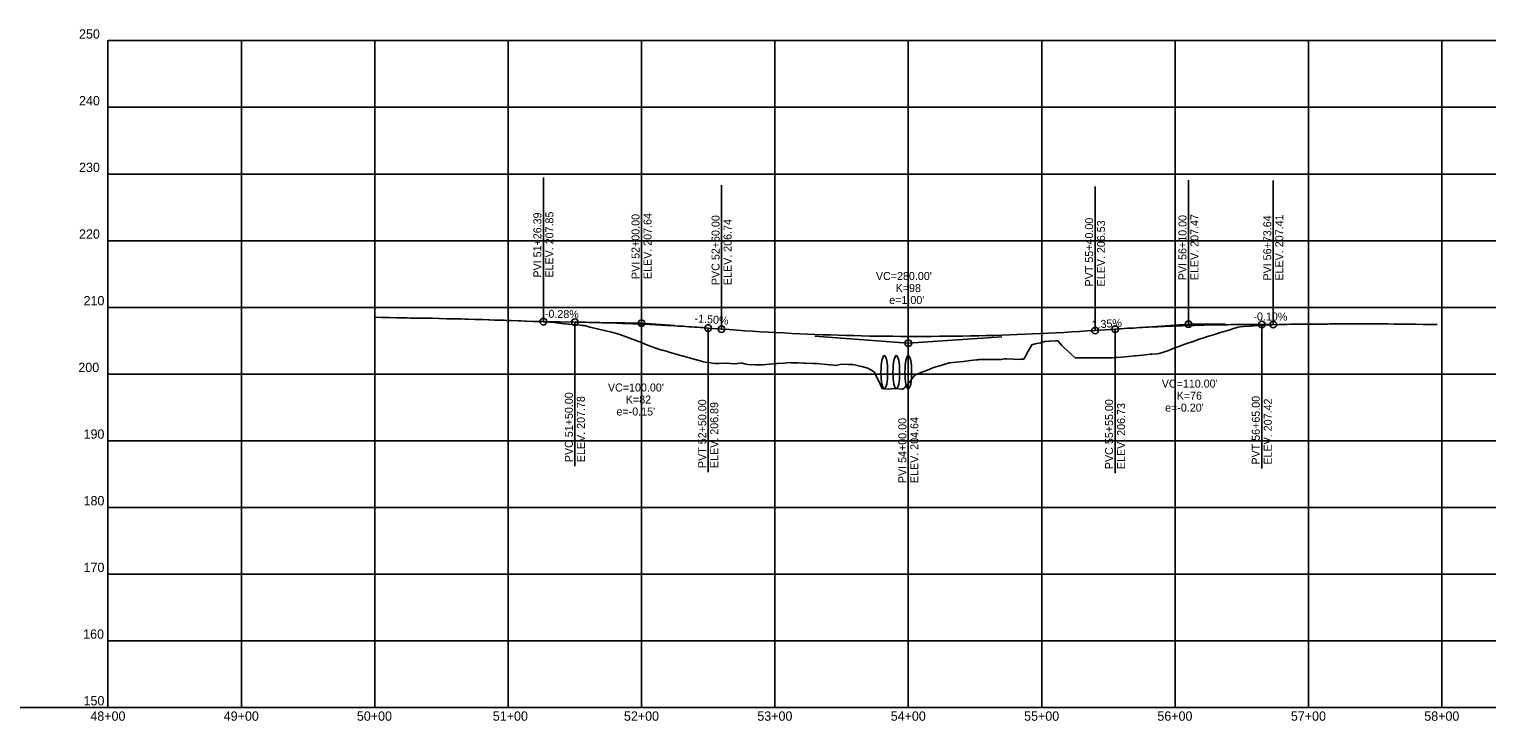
# Model space of a CAD drawing. Extents: x 1138442 to 1165793, y 1654070 to 1657687.
# Drawn here: x 1148047 to 1149139, y 1655043 to 1655562 of the extents above; entities that cross this region are included whole.
import ezdxf

# ---------------------------------------------------------------- set-up
doc = ezdxf.new("R2010")
doc.units = 0
for name, color, linetype in [('B_Dimensions', 7, 'Continuous'), ('R_Axis', 7, 'Continuous'), ('R_Axis Annot', 7, 'Continuous'), ('R_Concrete', 7, 'Continuous'), ('R_Grid', 7, 'Continuous'), ('R_No Plot', 7, 'Continuous'), ('R_Proposed Const Limits_Hand', 7, 'Continuous'), ('R_Vert Alg Annot', 7, 'Continuous')]:
    doc.layers.add(name, color=color, linetype=linetype)

msp = doc.modelspace()

# ---------------------------------------------------------------- linework, layer by layer
at = {"layer": 'B_Dimensions'}
for p, q in [((1148432.1, 1655342.7), (1148455.7, 1655342.3)), ((1148480.7, 1655342), (1148505.7, 1655341.6)), ((1148505.7, 1655341.6), (1148530.7, 1655339.7)), ((1148888.2, 1655338.9), (1148915.7, 1655340.8)), ((1148915.7, 1655340.8), (1148943.2, 1655340.7)), ((1148555.7, 1655337.9), (1148565.7, 1655337.1)), ((1148635.7, 1655331.9), (1148705.7, 1655326.6)), ((1148705.7, 1655326.6), (1148775.7, 1655331.3)), ((1148845.7, 1655336.1), (1148860.7, 1655337.1)), ((1148970.7, 1655340.5), (1148979.3, 1655340.5))]:
    msp.add_line(p, q, dxfattribs=at)
for points in [[(1148455.7, 1655342.3), (1148457.8, 1655342.3), (1148459.9, 1655342.3), (1148462, 1655342.2), (1148464, 1655342.2), (1148466.1, 1655342.1), (1148468.2, 1655342.1), (1148470.3, 1655342.1), (1148472.4, 1655342), (1148474.5, 1655342), (1148476.5, 1655341.9), (1148478.6, 1655341.8), (1148480.7, 1655341.8), (1148482.8, 1655341.7), (1148484.9, 1655341.7), (1148487, 1655341.6), (1148489, 1655341.5), (1148491.1, 1655341.4), (1148493.2, 1655341.4), (1148495.3, 1655341.3), (1148497.4, 1655341.2), (1148499.5, 1655341.1), (1148501.5, 1655341), (1148503.6, 1655340.9), (1148507.8, 1655340.8), (1148509.9, 1655340.7), (1148512, 1655340.6), (1148514, 1655340.5), (1148516.1, 1655340.4), (1148518.2, 1655340.3), (1148520.3, 1655340.1), (1148522.4, 1655340), (1148524.5, 1655339.9), (1148526.5, 1655339.8), (1148528.6, 1655339.7), (1148530.7, 1655339.6), (1148532.8, 1655339.4), (1148534.9, 1655339.3), (1148537, 1655339.2), (1148539, 1655339), (1148541.1, 1655338.9), (1148543.2, 1655338.8), (1148545.3, 1655338.6), (1148547.4, 1655338.5), (1148549.5, 1655338.3), (1148551.5, 1655338.2), (1148553.6, 1655338), (1148555.7, 1655337.9)], [(1148565.7, 1655337.1), (1148571.5, 1655336.7), (1148577.4, 1655336.3), (1148583.2, 1655335.9), (1148589, 1655335.5), (1148594.9, 1655335.1), (1148600.7, 1655334.8), (1148606.5, 1655334.5), (1148612.4, 1655334.2), (1148618.2, 1655333.9), (1148624, 1655333.6), (1148629.9, 1655333.4), (1148635.7, 1655333.1), (1148641.5, 1655332.9), (1148647.4, 1655332.7), (1148653.2, 1655332.5), (1148659, 1655332.3), (1148664.9, 1655332.2), (1148670.7, 1655332.1), (1148676.5, 1655331.9), (1148682.4, 1655331.8), (1148688.2, 1655331.8), (1148694, 1655331.7), (1148699.9, 1655331.6), (1148711.5, 1655331.6), (1148717.4, 1655331.6), (1148723.2, 1655331.6), (1148729, 1655331.7), (1148734.9, 1655331.7), (1148740.7, 1655331.8), (1148746.5, 1655331.9), (1148752.4, 1655332), (1148758.2, 1655332.1), (1148764, 1655332.3), (1148769.9, 1655332.4), (1148775.7, 1655332.6), (1148781.5, 1655332.8), (1148787.4, 1655333), (1148793.2, 1655333.2), (1148799, 1655333.5), (1148804.9, 1655333.7), (1148810.7, 1655334), (1148816.5, 1655334.3), (1148822.4, 1655334.6), (1148828.2, 1655335), (1148834, 1655335.3), (1148839.9, 1655335.7), (1148845.7, 1655336.1)], [(1148860.7, 1655337.1), (1148863, 1655337.2), (1148865.3, 1655337.4), (1148867.6, 1655337.5), (1148869.9, 1655337.7), (1148872.2, 1655337.8), (1148874.5, 1655337.9), (1148876.7, 1655338.1), (1148879, 1655338.2), (1148881.3, 1655338.3), (1148883.6, 1655338.5), (1148885.9, 1655338.6), (1148888.2, 1655338.7), (1148890.5, 1655338.8), (1148892.8, 1655338.9), (1148895.1, 1655339), (1148897.4, 1655339.1), (1148899.7, 1655339.2), (1148902, 1655339.3), (1148904.2, 1655339.4), (1148906.5, 1655339.5), (1148908.8, 1655339.6), (1148911.1, 1655339.6), (1148913.4, 1655339.7), (1148918, 1655339.9), (1148920.3, 1655339.9), (1148922.6, 1655340), (1148924.9, 1655340.1), (1148927.2, 1655340.1), (1148929.5, 1655340.2), (1148931.7, 1655340.2), (1148934, 1655340.3), (1148936.3, 1655340.3), (1148938.6, 1655340.3), (1148940.9, 1655340.4), (1148943.2, 1655340.4), (1148945.5, 1655340.4), (1148947.8, 1655340.5), (1148950.1, 1655340.5), (1148952.4, 1655340.5), (1148954.7, 1655340.5), (1148957, 1655340.5), (1148959.2, 1655340.5), (1148961.5, 1655340.5), (1148963.8, 1655340.5), (1148966.1, 1655340.5), (1148968.4, 1655340.5), (1148970.7, 1655340.5)]]:
    msp.add_lwpolyline(points, dxfattribs=at)
at = {"layer": 'R_Axis'}
for q in [(1148105.7, 1655553.4), (1149605.7, 1655053.4)]:
    msp.add_line((1148105.7, 1655053.4), q, dxfattribs=at)
at = {"layer": 'R_Concrete'}
for centre in [(1148687.7, 1655304.7), (1148696.7, 1655304.7), (1148705.7, 1655304.7)]:
    msp.add_ellipse(centre, major_axis=(0, -12.5), ratio=0.2, dxfattribs=at)
at = {"layer": 'R_Grid'}
for p, q in [((1148105.7, 1655553.4), (1149605.7, 1655553.4)), ((1148105.7, 1655553.4), (1149605.7, 1655553.4)), ((1148205.7, 1655053.4), (1148205.7, 1655553.4)), ((1148305.7, 1655053.4), (1148305.7, 1655553.4)), ((1148405.7, 1655053.4), (1148405.7, 1655553.4)), ((1148505.7, 1655053.4), (1148505.7, 1655553.4)), ((1148605.7, 1655053.4), (1148605.7, 1655553.4)), ((1148705.7, 1655053.4), (1148705.7, 1655553.4)), ((1148805.7, 1655053.4), (1148805.7, 1655553.4)), ((1148905.7, 1655053.4), (1148905.7, 1655553.4)), ((1149005.7, 1655053.4), (1149005.7, 1655553.4)), ((1149105.7, 1655053.4), (1149105.7, 1655553.4)), ((1148105.7, 1655503.4), (1149605.7, 1655503.4)), ((1148105.7, 1655453.4), (1149605.7, 1655453.4)), ((1148105.7, 1655403.4), (1149605.7, 1655403.4)), ((1148105.7, 1655353.4), (1149605.7, 1655353.4)), ((1148105.7, 1655303.4), (1149605.7, 1655303.4)), ((1148105.7, 1655253.4), (1149605.7, 1655253.4)), ((1148105.7, 1655203.4), (1149605.7, 1655203.4)), ((1148105.7, 1655153.4), (1149605.7, 1655153.4)), ((1148105.7, 1655103.4), (1149605.7, 1655103.4))]:
    msp.add_line(p, q, dxfattribs=at)
at = {"layer": 'R_No Plot'}
msp.add_line((1148105.7, 1655053.4), (1146536.5, 1655053.4), dxfattribs=at)
at = {"layer": 'R_Proposed Const Limits_Hand'}
msp.add_lwpolyline([(1148305.7, 1655346), (1148311.1, 1655345.8), (1148313.4, 1655345.8), (1148316.5, 1655345.7), (1148321.8, 1655345.6), (1148327.2, 1655345.5), (1148328, 1655345.5), (1148329.9, 1655345.5), (1148332.6, 1655345.4), (1148338, 1655345.4), (1148343.4, 1655345.3), (1148346.1, 1655345.3), (1148346.2, 1655345.3), (1148347, 1655345.2), (1148348.8, 1655345.2), (1148354.1, 1655345.1), (1148359.5, 1655344.9), (1148364.9, 1655344.8), (1148368.9, 1655344.7), (1148370.3, 1655344.7), (1148370.8, 1655344.7), (1148373.2, 1655344.6), (1148375.7, 1655344.5), (1148381, 1655344.4), (1148386.4, 1655344.2), (1148391, 1655344.1), (1148391.8, 1655344.1), (1148395.7, 1655343.9), (1148397.2, 1655343.9), (1148402.6, 1655343.7), (1148404.3, 1655343.6), (1148408, 1655343.5), (1148413.3, 1655343.3), (1148415.2, 1655343.3), (1148418.7, 1655343.1), (1148419.4, 1655343.1), (1148424.1, 1655342.9), (1148429.5, 1655342.7), (1148432, 1655342.7), (1148432.6, 1655342.6), (1148434.9, 1655342.5), (1148435.5, 1655342.5), (1148437, 1655342.4), (1148437.4, 1655342.4), (1148440.2, 1655342.1), (1148445.6, 1655341.4), (1148448.4, 1655341.1), (1148451, 1655340.9), (1148456.4, 1655340.3), (1148459.7, 1655340), (1148461.1, 1655339.8), (1148461.8, 1655339.8), (1148462.7, 1655339.7), (1148467.1, 1655338.6), (1148472.5, 1655337.3), (1148475.6, 1655336.5), (1148477.9, 1655336), (1148483.3, 1655334.9), (1148483.3, 1655334.9), (1148488.7, 1655333.2), (1148492.1, 1655332), (1148494.1, 1655331.3), (1148499.4, 1655329.3), (1148504.3, 1655327.5), (1148504.8, 1655327.3), (1148510.2, 1655325.1), (1148515.6, 1655323), (1148516.3, 1655322.7), (1148521, 1655321.3), (1148521.3, 1655321.2), (1148525.1, 1655320.2), (1148526.3, 1655319.8), (1148531.7, 1655318.2), (1148536, 1655317), (1148537.1, 1655316.7), (1148542.5, 1655315.3), (1148543.2, 1655315.1), (1148547.9, 1655313.7), (1148552.1, 1655312.5), (1148553.2, 1655312.3), (1148557.6, 1655311.7), (1148558.6, 1655311.6), (1148561, 1655311.3), (1148564, 1655311.4), (1148568.9, 1655311.6), (1148569.4, 1655311.6), (1148574.8, 1655311.1), (1148575.1, 1655311.1), (1148580.2, 1655311.6), (1148580.5, 1655311.7), (1148583.8, 1655310.7), (1148585.5, 1655310.6), (1148590.9, 1655310.3), (1148594.1, 1655310.2), (1148596.3, 1655310.3), (1148601.7, 1655310.8), (1148607.1, 1655311.2), (1148612.4, 1655311.6), (1148616.9, 1655312), (1148617.8, 1655311.9), (1148623.2, 1655311.8), (1148627.1, 1655311.6), (1148628.6, 1655311.6), (1148634, 1655311.4), (1148637.4, 1655311.3), (1148639.4, 1655311.1), (1148644.7, 1655310.5), (1148650.1, 1655310), (1148651, 1655309.9), (1148655.5, 1655310.7), (1148655.7, 1655310.7), (1148660.9, 1655310.6), (1148664, 1655310.5), (1148666.3, 1655310), (1148671.6, 1655308.7), (1148675.4, 1655307.9), (1148677, 1655306.9), (1148680.4, 1655304.7), (1148682.4, 1655300.3), (1148683, 1655299), (1148686, 1655292.5), (1148687.8, 1655292.4), (1148690.6, 1655292.1), (1148693.2, 1655292.3), (1148695.5, 1655292.5), (1148698.5, 1655292.3), (1148700.8, 1655292.1), (1148701.7, 1655292), (1148702.6, 1655292.9), (1148703.9, 1655294.3), (1148706.5, 1655297), (1148707.8, 1655299.1), (1148709.3, 1655301), (1148710.5, 1655302.5), (1148714.7, 1655304.2), (1148720.1, 1655306.4), (1148724.7, 1655308.3), (1148725.5, 1655308.5), (1148730.8, 1655310.1), (1148736.2, 1655311.7), (1148736.7, 1655311.9), (1148739, 1655312.1), (1148741.6, 1655312.4), (1148747, 1655312.9), (1148752.4, 1655313.5), (1148756.7, 1655314), (1148757.7, 1655314.1), (1148758.5, 1655314.2), (1148763.1, 1655314.2), (1148768.5, 1655314.3), (1148773.9, 1655314.3), (1148774.4, 1655314.3), (1148775.2, 1655314.4), (1148777.8, 1655314.8), (1148779.3, 1655314.8), (1148784.6, 1655314.5), (1148786.5, 1655314.4), (1148790, 1655314.5), (1148792.2, 1655314.6), (1148793.3, 1655316.2), (1148795.4, 1655320), (1148798.4, 1655325.4), (1148800.8, 1655326), (1148804.8, 1655326.9), (1148806.2, 1655327.3), (1148808, 1655327.9), (1148811.6, 1655328), (1148816.3, 1655328.2), (1148816.9, 1655328.2), (1148817.9, 1655328.3), (1148820.8, 1655324.8), (1148822.3, 1655323.4), (1148827.7, 1655318.4), (1148831, 1655315.4), (1148831.2, 1655315.5), (1148833.1, 1655315.5), (1148838.5, 1655315.5), (1148843.8, 1655315.5), (1148844.2, 1655315.5), (1148845.1, 1655315.5), (1148849.2, 1655315.5), (1148854.6, 1655315.6), (1148857.5, 1655315.6), (1148858.7, 1655315.6), (1148860, 1655315.7), (1148861.7, 1655315.7), (1148865.4, 1655316.1), (1148870.8, 1655316.6), (1148875, 1655317), (1148876.1, 1655317.1), (1148881.5, 1655317.6), (1148881.6, 1655317.6), (1148886.9, 1655318.2), (1148888.2, 1655318.3), (1148892.3, 1655318.6), (1148893.8, 1655318.8), (1148897.7, 1655320.1), (1148900.2, 1655320.9), (1148903, 1655322), (1148905, 1655322.7), (1148908.4, 1655324), (1148913, 1655325.7), (1148913.8, 1655326), (1148919.2, 1655327.9), (1148922.5, 1655329.1), (1148924.6, 1655329.7), (1148926.5, 1655330.3), (1148929.3, 1655331.3), (1148929.9, 1655331.5), (1148935.3, 1655333.1), (1148940.4, 1655334.7), (1148940.7, 1655334.8), (1148946.1, 1655336.4), (1148950.2, 1655337.7), (1148951.5, 1655338), (1148952.1, 1655338.2), (1148954.4, 1655338.9), (1148956.9, 1655339), (1148962, 1655339.2), (1148962.2, 1655339.2), (1148967.6, 1655339.7), (1148971.7, 1655340.1), (1148972.3, 1655340.1), (1148973, 1655340.2), (1148973, 1655340.2), (1148973.6, 1655340.2), (1148978.4, 1655340.4), (1148978.8, 1655340.4), (1148983.8, 1655340.5), (1148989.1, 1655340.6), (1148992.1, 1655340.7), (1148994.5, 1655340.7), (1148996, 1655340.7), (1148999.9, 1655340.8), (1149005.3, 1655340.8), (1149006.1, 1655340.8), (1149010.7, 1655340.9), (1149013.3, 1655340.9), (1149016, 1655340.9), (1149020.3, 1655340.9), (1149021.4, 1655341), (1149025.4, 1655341), (1149026.8, 1655341), (1149032.2, 1655341), (1149034.5, 1655341), (1149037.6, 1655341), (1149037.9, 1655341), (1149043, 1655341.1), (1149048.3, 1655341.1), (1149048.8, 1655341.1), (1149051.1, 1655341.1), (1149053.7, 1655341), (1149059.1, 1655341), (1149064, 1655341), (1149064.5, 1655341), (1149065.1, 1655341), (1149069.9, 1655340.9), (1149075.2, 1655340.9), (1149079.3, 1655340.8), (1149079.5, 1655340.8), (1149080.6, 1655340.8), (1149085, 1655340.8), (1149086, 1655340.7), (1149091.4, 1655340.6), (1149094.4, 1655340.6), (1149094.6, 1655340.6), (1149096.8, 1655340.5), (1149102.2, 1655340.5)], dxfattribs=at)
at = {"layer": 'R_Vert Alg Annot'}
for p, q in [((1148432.1, 1655372.7), (1148432.1, 1655450.7)), ((1148505.7, 1655371.6), (1148505.7, 1655449.6)), ((1148565.7, 1655367.1), (1148565.7, 1655445.1)), ((1148845.7, 1655366.1), (1148845.7, 1655444.1)), ((1148915.7, 1655370.8), (1148915.7, 1655448.8)), ((1148979.3, 1655370.5), (1148979.3, 1655448.5)), ((1148432.1, 1655342.7), (1148432.1, 1655372.7)), ((1148505.7, 1655341.6), (1148505.7, 1655371.6)), ((1148565.7, 1655337.1), (1148565.7, 1655367.1)), ((1148845.7, 1655336.1), (1148845.7, 1655366.1)), ((1148915.7, 1655340.8), (1148915.7, 1655370.8)), ((1148979.3, 1655340.5), (1148979.3, 1655370.5)), ((1148455.7, 1655342.3), (1148455.7, 1655312.3)), ((1148555.7, 1655337.9), (1148555.7, 1655307.9)), ((1148860.7, 1655337.1), (1148860.7, 1655307.1)), ((1148970.7, 1655340.5), (1148970.7, 1655310.5)), ((1148705.7, 1655326.6), (1148705.7, 1655296.6)), ((1148455.7, 1655312.3), (1148455.7, 1655234.3)), ((1148555.7, 1655307.9), (1148555.7, 1655229.9)), ((1148970.7, 1655310.5), (1148970.7, 1655232.5)), ((1148860.7, 1655307.1), (1148860.7, 1655229.1)), ((1148705.7, 1655296.6), (1148705.7, 1655218.6))]:
    msp.add_line(p, q, dxfattribs=at)
for centre in [(1148432.1, 1655342.7), (1148455.7, 1655342.3), (1148505.7, 1655341.6), (1148915.7, 1655340.8), (1148970.7, 1655340.5), (1148979.3, 1655340.5), (1148555.7, 1655337.9), (1148565.7, 1655337.1), (1148845.7, 1655336.1), (1148860.7, 1655337.1), (1148705.7, 1655326.6)]:
    msp.add_circle(centre, 2.5, dxfattribs=at)

# ---------------------------------------------------------------- texts
at = {"layer": 'R_Axis Annot'}
for s, height, p in [('250', 7, (1148084, 1655554.9)), ('250', 7, (1148084, 1655554.9)), ('240', 7, (1148084, 1655504.9)), ('230', 7, (1148084, 1655454.9)), ('220', 7, (1148084, 1655404.9)), ('210', 7, (1148087.4, 1655354.9)), ('200', 7, (1148083.5, 1655304.9)), ('190', 7, (1148087.4, 1655254.9)), ('180', 7, (1148087.4, 1655204.9)), ('170', 7, (1148087.4, 1655154.9)), ('160', 7, (1148087.1, 1655104.9)), ('150', 7, (1148087.4, 1655054.9)), ('48+00', 7, (1148092.5, 1655043.4)), ('-', 0.0001, (1148105.7, 1655053.4)), ('49+00', 7, (1148192.5, 1655043.4)), ('50+00', 7, (1148292.3, 1655043.4)), ('51+00', 7, (1148394.2, 1655043.4)), ('52+00', 7, (1148492.5, 1655043.4)), ('53+00', 7, (1148592.5, 1655043.4)), ('54+00', 7, (1148692.5, 1655043.4)), ('55+00', 7, (1148792.5, 1655043.4)), ('56+00', 7, (1148892.4, 1655043.4)), ('57+00', 7, (1148992.5, 1655043.4)), ('58+00', 7, (1149092.5, 1655043.4))]:
    msp.add_text(s, height=height, dxfattribs=at).set_placement(p)
at = {"layer": 'R_Vert Alg Annot'}
for s, rotation, p in [('PVI 51+26.39', 90, (1148430.6, 1655375.7)), ('ELEV. 207.85', 90, (1148439.6, 1655375.7)), ('PVI 52+00.00', 90, (1148504.2, 1655374.6)), ('ELEV. 207.64', 90, (1148513.2, 1655374.6)), ('PVC 52+60.00', 90, (1148564.2, 1655370.1)), ('ELEV. 206.74', 90, (1148573.2, 1655370.1)), ('PVT 55+40.00', 90, (1148844.2, 1655369.1)), ('ELEV. 206.53', 90, (1148853.2, 1655369.1)), ('PVI 56+10.00', 90, (1148914.2, 1655373.8)), ('ELEV. 207.47', 90, (1148923.2, 1655373.8)), ('PVI 56+73.64', 90, (1148977.8, 1655373.5)), ('ELEV. 207.41', 90, (1148986.8, 1655373.5)), ('-0.28%', 359.1979, (1148433.2, 1655345.6)), ('-1.50%', 355.7108, (1148545.3, 1655342.3)), ('1.35%', 3.8616, (1148843.3, 1655337.4)), ('-0.10%', 359.7135, (1148964.4, 1655343.6)), ('PVC 51+50.00', 90, (1148454.2, 1655237.3)), ('ELEV. 207.78', 90, (1148463.2, 1655237.3)), ('PVT 56+65.00', 90, (1148969.2, 1655235.5)), ('PVT 52+50.00', 90, (1148554.2, 1655232.9)), ('ELEV. 206.89', 90, (1148563.2, 1655232.9)), ('PVC 55+55.00', 90, (1148859.2, 1655232.1)), ('ELEV. 206.73', 90, (1148868.2, 1655232.1)), ('ELEV. 207.42', 90, (1148978.2, 1655235.5)), ('PVI 54+00.00', 90, (1148704.2, 1655221.6)), ('ELEV. 204.64', 90, (1148713.2, 1655221.6))]:
    msp.add_text(s, height=6, rotation=rotation, dxfattribs=at).set_placement(p)
for s, p in [("VC=280.00'", (1148681.4, 1655373.9)), ('K=98', (1148696.2, 1655364.9)), ("e=1.00'", (1148691.4, 1655355.9)), ("VC=110.00'", (1148895.7, 1655293.2)), ("VC=100.00'", (1148480.5, 1655290.3)), ('K=82', (1148493.9, 1655281.3)), ('K=76', (1148906.9, 1655284.2)), ("e=-0.15'", (1148486.9, 1655272.3)), ("e=-0.20'", (1148898.2, 1655275.2))]:
    msp.add_text(s, height=6, dxfattribs=at).set_placement(p)

doc.saveas('drawing.dxf')
